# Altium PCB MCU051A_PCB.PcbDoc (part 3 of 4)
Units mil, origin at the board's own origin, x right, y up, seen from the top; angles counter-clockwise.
Board outline 4000 x 6000 mil, 6 copper layers (Top Layer, Signal Layer 1, Signal Layer 2, Signal Layer 3, Signal Layer 4, Bottom Layer), stack 60.4 mil thick; 193 components, 239 nets, 864 pads, 621 vias.
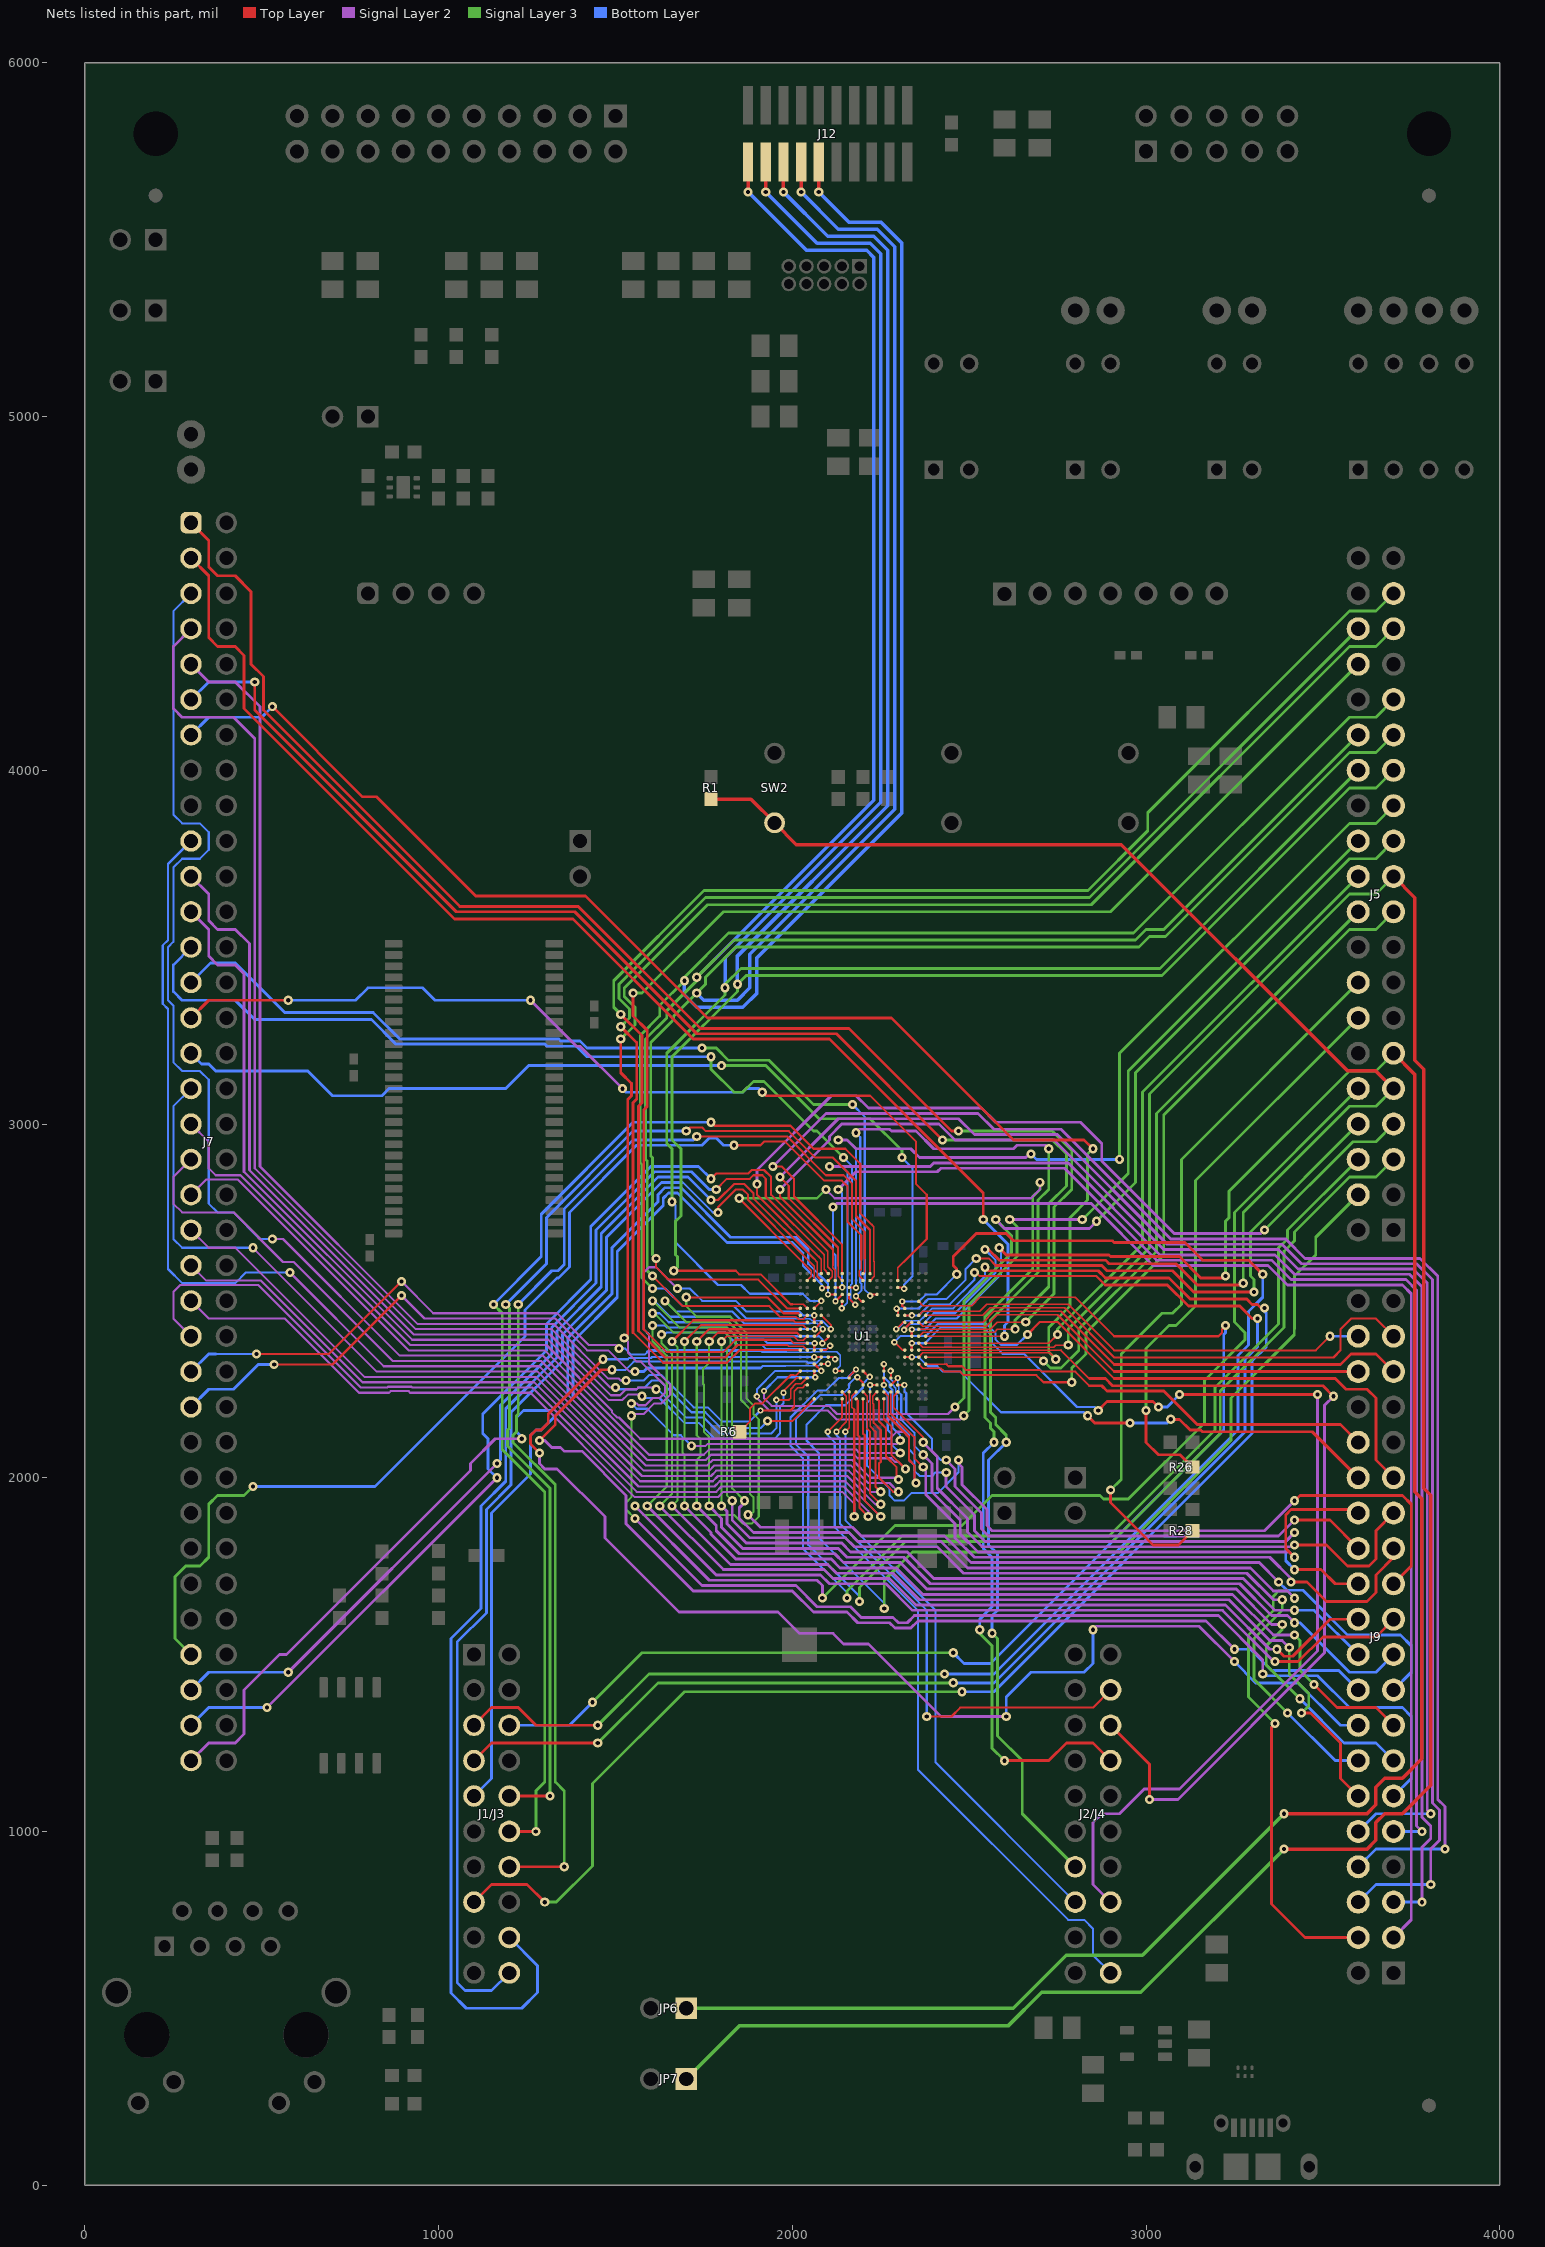
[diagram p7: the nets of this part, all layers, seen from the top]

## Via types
v1: diameter 26, hole 12, Top Layer to Bottom Layer, tented both sides, 517 vias
v2: diameter 18, hole 8, Top Layer to Bottom Layer, tented both sides, 94 vias
v3: diameter 26, hole 12, Top Layer to Bottom Layer, 7 vias
v4: diameter 19.68, hole 7.87, Top Layer to Bottom Layer, 2 vias
v5: diameter 18, hole 8, Top Layer to Bottom Layer, 1 vias

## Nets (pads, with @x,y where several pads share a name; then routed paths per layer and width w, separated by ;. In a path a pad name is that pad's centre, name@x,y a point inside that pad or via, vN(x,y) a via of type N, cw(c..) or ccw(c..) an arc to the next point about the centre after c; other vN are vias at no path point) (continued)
PE5: J1/J3.23 U1.B5 | length 3633.6
  Top Layer w4: U1.B5@2357.48,2498.43 2369.17,2486.74 2506.74,2486.74 2530,2510 2800,2510
  Top Layer w6: 2800,2510 2910,2400 3205,2400 3215,2410 3215,2420 v1(3225,2430)
  Signal Layer 3 w8: v1(1435,1365) 1575,1505 v1(2455,1505)
  Bottom Layer w8: J1/J3.23@1200,1300 1370,1300 v1(1435,1365) ; v1(2455,1505) 2485,1475 2560,1475 3220,2135 3220,2405 3225,2410 v1(3225,2430)
PE6: J9.37 U1.A7 | length 1490.9
  Top Layer w4: U1.A7@2377.17,2459.06 2539.06,2459.06 2560,2480 2770,2480
  Top Layer w6: 2770,2480 2910,2340 3530,2340 3550,2360 3550,2420 3580,2450 3650,2450 J9.37@3700,2400
PE7: J9.38 U1.B7 | length 1325.8
  Top Layer w4: U1.B7@2357.48,2459.06 2358.32,2459.06 2369.26,2470 2530,2470 2550,2490 2780,2490
  Top Layer w6: 2780,2490 2910,2360 3480,2360 v1(3520,2400)
  Bottom Layer w8: v1(3520,2400) J9.38@3600,2400
PF0: J5.28 J12.18 U1.U6 | length 6098.7
  Top Layer w4: v2@2082,2498.54 v2(2082,2500)
  Top Layer w6: U1.U6@2062.2,2478.74 v2@2082,2498.54
  Top Layer w10: v1(1925,5635) J12.18@1925,5719.88
  Signal Layer 3 w8: v1(1660,2780) 1660,2930 1645,2945 1645,3200 1810,3365 v1(1810,3385) 1810,3395 1855,3440 3040,3440 J5.28@3600,4000
  Bottom Layer w6: v1(1660,2780) 1670,2770 1670,2665 1790,2545 1855,2545 1880,2520 2030,2520 2050,2500 v2(2082,2500)
  Bottom Layer w10: v1(1810,3385) 1810,3470 2250,3910 2250,5460 2220,5490 2070,5490 v1(1925,5635)
PF1: J5.27 J12.16 U1.V6 | length 6135.8
  Top Layer w4: 2000,2490.43 2030.83,2490.43 U1.V6@2042.52,2478.74
  Top Layer w6: v1(1665,2585) 1840,2585 1850,2575 1910.43,2575 1995,2490.43 2000,2490.43
  Top Layer w10: v1(1975,5635) J12.16@1975,5719.88
  Signal Layer 3 w8: v1(1665,2585) 1675,2595 1675,2625 1670,2630 1670,2725 1685,2740 1685,2930 1660,2955 1660,3190 1845,3375 v1(1845,3395) 1870,3420 3045,3420 3575,3950 3650,3950 J5.27@3700,4000
  Bottom Layer w10: v1(1845,3395) 1845,3475 2270,3900 2270,5470 2230,5510 2100,5510 v1(1975,5635)
PF2: J5.29 J12.14 U1.W6 | length 6426.8
  Top Layer w6: v1(1615,2620) 1615,2595 1650,2560 1903.74,2560 1985,2478.74 U1.W6@2022.83,2478.74
  Top Layer w10: v1(2025,5635) J12.14@2025,5719.88
  Signal Layer 3 w8: v1(1615,2620) 1605,2630 1605,2905 1600,2910 1600,3230 1665,3295 1665,3305 v1(1730,3370) 1755,3395 1755,3415 1840,3500 2980,3500 3010,3530 3055,3530 3575,4050 3650,4050 J5.29@3700,4100
  Bottom Layer w10: v1(1730,3370) 1750,3350 1845,3350 1880,3385 1880,3480 2290,3890 2290,5480 2240,5530 2130,5530 v1(2025,5635)
PF3: J5.31 J12.12 U1.T7 | length 6824.2
  Top Layer w6: U1.T7@2081.89,2459.06 2109,2431.95 v2(2109,2420)
  Top Layer w10: v1(2075,5635) J12.12@2075,5719.88
  Signal Layer 3 w8: v1(1605,2535) 1575,2565 1575,2885 1570,2890 1570,3250 1625,3305 1625,3335 v1(1695,3405) 1695,3415 1820,3540 2965,3540 3575,4150 3650,4150 J5.31@3700,4200
  Bottom Layer w4: 2020,2450 2049.99,2450 2055.99,2444 2085,2444 v2(2109,2420)
  Bottom Layer w6: v1(1605,2535) 1640,2535 1690,2485 1835,2485 1870,2450 2020,2450
  Bottom Layer w10: v1(1695,3405) 1695,3365 1730,3330 1860,3330 1900,3370 1900,3470 2310,3880 2310,5490 2250,5550 2160,5550 v1(2075,5635)
PF4: J5.30 J12.20 U1.V7 | length 6318.9
  Top Layer w4: 1960,2460 1965,2455 2010,2455 2017.63,2447.37 2030.83,2447.37 U1.V7@2042.52,2459.06
  Top Layer w6: v1(1605,2570) 1690,2485 1935,2485 1960,2460
  Top Layer w10: v1(1875,5635) J12.20@1875,5719.88
  Signal Layer 3 w8: v1(1605,2570) 1590,2585 1590,2895 1585,2900 1585,3240 1645,3300 1645,3320 1730,3405 v1(1730,3415) 1835,3520 2970,3520 3000,3550 3050,3550 J5.30@3600,4100
  Bottom Layer w10: v1(1730,3415) 2230,3915 2230,5450 2210,5470 2040,5470 v1(1875,5635)
PF5: J5.10 U1.W7 | length 4585
  Top Layer w6: v1(1700,2510) 1930,2510 1975,2465 2016.89,2465 U1.W7@2022.83,2459.06
  Signal Layer 2 w8: v1(1555,1920) 1765,1710 2070,1710 2085,1695 v1(2085,1660)
  Signal Layer 3 w6: v1(1555,1920) 1580,1895 1835,1895 1860,1870 1885,1870 1905,1890 1905,2165 1890,2180 1890,2205 1870,2225 1870,2410 1825,2455 1730,2455 1700,2485 v1(1700,2510)
  Signal Layer 3 w8: v1(2085,1660) 2290,1865 2480,1865 2565,1950 2870,1950 2880,1940 2950,1940 3165,2155 3165,2275 3280,2390 3280,2410 3250,2440 3250,2750 J5.10@3600,3100
PF6: J9.4 U1.T8 | length 4292.7
  Top Layer w6: v2(2063,2420) 2081.89,2438.89 U1.T8@2081.89,2439.37
  Top Layer w8: v1(3365,1305) 3355,1295 3355,795 3450,700 J9.4@3600,700
  Signal Layer 2 w8: v1(1865,1935) 1865,1930 1850,1915 1850,1885 1890,1845 2160,1845 2185,1820 2420,1820 2495,1745 3295,1745 3360,1680 3400,1680 3420,1660 v1(3420,1659)
  Signal Layer 3 w6: v1(1605,2500) 1680,2425 1814.69,2425 1840,2399.69 1840,2370 1830,2360 1830,1970 v1(1865,1935)
  Signal Layer 3 w8: v1(3365,1305) 3290,1380 3290,1555 3360,1625 3360,1665 3375,1680 3400,1680 3420,1660 v1(3420,1659)
  Bottom Layer w6: v1(1605,2500) 1610,2500 1655,2455 1825,2455 1860,2420 v2(2063,2420)
PF7: J9.11 U1.U8 | length 4094.5
  Top Layer w6: U1.U8@2062.2,2439.37 v2(2062.2,2459)
  Signal Layer 2 w6: v1(1545,2175) 1550,2180 1580,2180 1610,2210 1630,2210 1655,2235 1655,2263 1595,2323 1595,2405 1580,2420 1580,2580 1595,2595 1615,2595 v1(1675,2535)
  Signal Layer 2 w8: v1(1555,1885) 1745,1695 2010,1695 2070,1635 2165,1635 2195,1605 2285,1605 2300,1590 2325,1590 2345,1610 3205,1610 3330,1485 v1(3330,1445)
  Signal Layer 3 w6: v1(1545,2175) 1545,1945 1530,1930 1530,1910 v1(1555,1885)
  Bottom Layer w6: v1(1675,2535) 1710,2535 1745,2500 1840,2500 1870,2470 2020,2470 2031,2459 v2(2062.2,2459)
  Bottom Layer w8: v1(3330,1445) 3335,1440 3485,1440 3575,1350 3725,1350 3750,1325 3750,1150 J9.11@3700,1100
PG0: J7.49 U1.N15 | length 2107.3
  Top Layer w6: v1(485,2350) 690,2350 v1(895,2555) ; v2@2122.43,2301.57 U1.N15@2140.94,2301.57
  Signal Layer 2 w6: v1(895,2555) 985,2465 1335,2465 1425,2375 1500,2375 v1(1510,2365)
  Bottom Layer w4: 1983,2355 2054.79,2355 2055.79,2356 2126,2356 2136,2346 2136,2316 v2(2122,2302)
  Bottom Layer w6: 370,2350 v1(485,2350) ; v1(1510,2365) 1528,2365 1545,2348 1583,2348 1590,2355 ; 1910,2360 1915,2355 1983,2355
  Bottom Layer w8: J7.49@300,2300 350,2350 370,2350 ; 1590,2355 1595,2360 1910,2360
PG1: J7.51 U1.T14 | length 2049.1
  Top Layer w6: v1(535,2320) 700,2320 v1(895,2515) ; U1.T14@2081.89,2321.26 2100.26,2321.26 v2(2101,2322)
  Signal Layer 2 w6: v1(895,2515) 960,2450 1330,2450 1420,2360 1480,2360 1540,2300 v1(1555,2300)
  Bottom Layer w4: 1980,2316 2074.79,2316 2080.79,2322 v2(2101,2322)
  Bottom Layer w6: 1910,2310 1916,2316 1980,2316
  Bottom Layer w8: J7.51@300,2200 350,2250 420,2250 490,2320 v1(535,2320) ; v1(1555,2300) 1580,2300 1590,2310 1910,2310
PG2: J5.34 U1.V11 | length 3913.5
  Top Layer w4: 1994.46,2390 2003.15,2381.32 ; 2003.15,2380.32 U1.V11@2042.52,2380.32
  Top Layer w6: 1580,2420 1645,2355 1805,2355 1840,2390 1994.46,2390
  Top Layer w8: v1(1550,3370) 1550,3305 1590,3265 1590,3050 1580,3040 1580,2420
  Signal Layer 3 w8: v1(1550,3370) 1575,3370 1805,3600 2900,3600 J5.34@3600,4300
PG3: J5.6 U1.M16 | length 3031
  Top Layer w6: U1.M16@2160.63,2281.89 2160.63,2286.63 v2(2180,2306)
  Signal Layer 3 w8: v1(2155,1660) 2155,1680 2310,1835 2895,1835 3195,2135 3195,2255 3375,2435 3375,2650 3400,2675 3400,2700 J5.6@3600,2900
  Bottom Layer w6: v1(2155,1660) 2155,1675 2030,1800 2030,2055 1995,2090 1995,2170 2071,2246 2095,2246 2130.89,2281.89 2155.89,2281.89 v2(2180,2306)
PG4: J5.5 U1.K17 | length 3109.6
  Top Layer w6: v2(2184,2284) 2200,2268 U1.K17@2200,2262.2
  Signal Layer 3 w8: v1(2190,1650) 2190,1690 2320,1820 2905,1820 3210,2125 3210,2245 3390,2425 3390,2640 3420,2670 3420,2695 3575,2850 3650,2850 J5.5@3700,2900
  Bottom Layer w6: v2(2184,2284) 2179.37,2284 2160.63,2265.26 2160.63,2254.63 2140,2234 2079,2234 2010,2165 2010,2095 2045,2060 2045,1810 2190,1665 v1(2190,1650)
PG5: J5.4 U1.K15 | length 2946.1
  Top Layer w6: U1.K15@2200,2301.57 2216.57,2285 v2(2219,2285)
  Signal Layer 3 w8: v1(2260,1630) 2260,1710 2340,1790 2925,1790 3240,2105 3240,2225 3419,2404 3419,2419.7 3420,2420.7 3420,2570 3480,2630 3480,2680 J5.4@3600,2800
  Bottom Layer w6: v2(2219,2285) 2200,2266 2200,2255 2150,2205 2095,2205 2040,2150 2040,2105 2075,2070 2075,1830 2260,1645 v1(2260,1630)
PG6: J5.37 U1.V12 | length 4244.7
  Top Layer w4: 1986.63,2375 1989.32,2372.32 2030.83,2372.32 2033.76,2369.39 U1.V12@2042.52,2360.63
  Top Layer w6: 1565,2415 1640,2340 1810,2340 1845,2375 1986.63,2375
  Top Layer w8: v1(1515,3310) 1575,3250 1575,3060 1565,3050 1565,2415
  Signal Layer 3 w8: v1(1515,3310) 1495,3330 1495,3405 1750,3660 2835.97,3660 3005,3829.03 3005,3880 3575,4450 3650,4450 J5.37@3700,4500
PG7: J5.24 U1.U14 | length 3093.8
  Top Layer w6: U1.U14@2062.2,2321.26 2062.74,2321.26 v2(2082,2302)
  Signal Layer 2 w6: v2(1900,2230) 1900,2225 1935,2190 2100,2190 2125,2165 2475,2165 v1(2485,2175)
  Signal Layer 2 w8: v1(2615,2730) v1(2820,2730)
  Signal Layer 3 w8: v1(2485,2175) 2500,2190 2500,2490 2635,2625 2635,2710 v1(2615,2730) ; v1(2820,2730) 2950,2860 2950,3150 J5.24@3600,3800
  Bottom Layer w6: v2(1900,2230) 1900,2250 1952,2302 v2(2082,2302)
PH0: J7.71 U1.P4 | length 2969.8
  Top Layer w4: v2(2101,2518) v2@2101.11,2518.11
  Top Layer w6: v2@2101.11,2518.11 U1.P4@2121.26,2518.11
  Signal Layer 2 w8: J7.71@300,1200 350,1250 425,1250 450,1275 450,1400 550,1500 570,1500 1090,2020 1090,2040 1160,2110 v1(1235,2110)
  Bottom Layer w6: 2045,2645 2045,2605 2101,2549 v2(2101,2518)
  Bottom Layer w8: v1@1230,2120 1220,2130 1220,2170 1240,2190 1320,2190 1365,2235 1365,2395 1490,2520 1490,2650 1620,2780 1620,2800 1640,2820 1685,2820 1825,2680 2010,2680 2045,2645
PH1: J7.69 U1.R2 | length 2989.9
  Top Layer w4: 2100,2640 2100,2596.85 2112.5,2584.35 2112.5,2568.4 U1.R2@2101.57,2557.48
  Top Layer w6: v1(1770,2845) 1785,2860 1875,2860 1885,2870 1920,2870 1940,2850 1940,2800 2100,2640
  Signal Layer 2 w8: v1(515,1350) v1(1165,2000)
  Bottom Layer w8: J7.69@300,1300 350,1350 v1(515,1350) ; v1(1165,2000) 1140,2025 1140,2110 1125,2125 1125,2180 1305,2360 1305,2435 1430,2560 1430,2710 1600,2880 1735,2880 v1(1770,2845)
PH2: J7.67 U1.R1 | length 2836.8
  Top Layer w4: 2090,2630 2090,2588.74 U1.R1@2101.57,2577.17
  Top Layer w6: v1(1785,2815) 1815,2845 1880,2845 1890,2855 1915,2855 1925,2845 1925,2795 2090,2630
  Signal Layer 2 w8: v1(575,1450) v1(1165,2040)
  Bottom Layer w8: J7.67@300,1400 350,1450 v1(575,1450) ; v1(1165,2040) 1175,2050 1175,2205 1320,2350 1320,2425 1445,2550 1445,2700 1610,2865 1715,2865 1765,2815 v1(1785,2815)
PH3: J5.7 U1.T1 | length 2574.4
  Top Layer w4: 2075,2625 2081.89,2618.11 U1.T1@2081.89,2577.17
  Top Layer w6: v1(1900,2830) 1900,2800 2075,2625
  Signal Layer 2 w8: v1(1900,2830) 1900,2870 2110,3080 2180,3080 2215,3045 2535,3045 2575,3005 2815,3005 2875,2945 2875,2895 3080,2690 3325,2690 v1(3335,2700)
  Signal Layer 3 w8: v1(3335,2700) 3585,2950 3650,2950 J5.7@3700,3000
PH4: J1/J3.5 U1.R3 | length 2531.7
  Top Layer w6: v2(2084,2536) 2085.8,2537.8 U1.R3@2101.57,2537.8
  Bottom Layer w6: 2030,2635 2030,2600 2084,2546 v2(2084,2536)
  Bottom Layer w8: J1/J3.5@1100,1100 1150,1150 1150,1900 1260,2010 1260,2120 1275,2135 1290,2135 1380,2225 1380,2385 1505,2510 1505,2640 1635,2770 1635,2790 1650,2805 1675,2805 1815,2665 2000,2665 2030,2635
PH5: J1/J3.29 U1.T2 | length 3671.8
  Top Layer w4: 2060,2620 2070.2,2609.8 2070.2,2570 2081.89,2558.32 U1.T2@2081.89,2557.48
  Top Layer w6: v1(1770,2785) 1790,2785 1835,2830 1865,2830 1890,2805 1890,2790 2060,2620
  Bottom Layer w8: J1/J3.29@1200,700 1280,620 1280,545 1235,500 1078,500 1035,543 1035,1545 1120,1630 1120,1920 1190,1990 1190,2195 1335,2340 1335,2415 1460,2540 1460,2690 1620,2850 1705,2850 v1(1770,2785)
PH6: J1/J3.30 U1.U2 | length 3321.4
  Top Layer w4: 2030,2630 2062.2,2597.8 U1.U2@2062.2,2557.48
  Top Layer w6: v1(1790,2750) 1790,2765 1840,2815 1860,2815 1875,2800 1875,2785 2030,2630
  Bottom Layer w6: 1690,2835 1775,2750 v1(1790,2750)
  Bottom Layer w8: J1/J3.30@1200,600 1150,550 1075,550 1052.5,572.5 1052.5,1535 1135,1617.5 1135,1910 1205,1980 1205,2185 1350,2330 1350,2405 1475,2530 1475,2680 1630,2835 1690,2835
PH7: J2/J4.17 U1.V2 | length 3340.3
  Top Layer w4: 2030,2609.2 2054.2,2585 2054.2,2570 2042.52,2558.31 U1.V2@2042.52,2557.48
  Top Layer w6: v1(1850,2790) 1850,2789.2 2030,2609.2
  Top Layer w8: v1(2600,1200) 2725,1200 2775,1250 2850,1250 J2/J4.17@2900,1200
  Signal Layer 2 w6: v1(2095,2815) 2120,2790 2675,2790 2700,2815 v1(2700,2835)
  Signal Layer 3 w6: v1(1850,2790) 2070,2790 v1(2095,2815)
  Signal Layer 3 w8: v1(2530,1570) 2530,1560 2565,1525 2565,1235 v1(2600,1200) ; v1(2570,2100) 2570,2130 2560,2140 2560,2155 2545,2170 2545,2455 2680,2590 2680,2795 2700,2815 v1(2700,2835)
  Bottom Layer w8: v1(2530,1570) 2530,1600 2565,1635 2565,1775 2540,1800 2540,2070 v1(2570,2100)
PJ0: J5.9 R1.1 SW2.2 U1.C8 | length 4247
  Top Layer w6: v2@2316,2419.63 2335.74,2439.37 U1.C8@2337.8,2439.37
  Top Layer w8: v1(2545,2645) 2555,2645 2585,2615 2885,2615 2895,2605 3085,2605 3145,2545 3270,2545 v1(3275,2550)
  Top Layer w10: R1.1@1770,3918.51 1883.07,3918.51 SW2.2@1950,3851.58 2011.58,3790 2930,3790 3570,3150 3650,3150 J5.9@3700,3100
  Signal Layer 3 w8: v1(3275,2550) 3275,2750 3575,3050 3650,3050 J5.9@3700,3100
  Bottom Layer w6: v2(2316,2418) 2316,2419.63 2331.37,2435 2370,2435 2400,2465 2460,2465 2575,2580 2575,2615 v1(2545,2645)
PJ1: J5.8 U1.E7 | length 1746.7
  Top Layer w6: U1.E7@2298.43,2459.06 v2@2298.43,2474.57 ; v1(2520,2620) 2555,2620 2575,2600
  Top Layer w8: 2575,2600 2875,2600 2890,2585 3075,2585 3135,2525 v1(3305,2525)
  Signal Layer 3 w8: v1(3305,2525) 3305,2560 3295,2570 3295,2695 J5.8@3600,3000
  Bottom Layer w6: v2(2295,2478) 2356.74,2478 2383.74,2505 2435,2505 2490,2560 2490,2590 v1(2520,2620)
PJ2: J9.23 U1.H17 | length 2352.3
  Top Layer w6: v2(2220,2262) 2220.2,2262.2 U1.H17@2239.37,2262.2
  Top Layer w8: v1(3420,1935) 3435,1950 3725,1950 3750,1925 3750,1750 J9.23@3700,1700
  Signal Layer 2 w8: v1(2470,2050) 2470,2040 2480,2030 2480,1980 2550,1910 2550,1865 2565,1850 3335,1850 v1(3420,1935)
  Bottom Layer w6: v2(2220,2262) 2220,2220 2211.69,2211.69 2211.69,2033.31 2275,1970 2275,1950 2290,1935 2315,1935 2336.5,1956.5 2411.5,1956.5 2470,2015 v1(2470,2050)
PJ3: J9.24 U1.F16 | length 1878.7
  Top Layer w6: v2(2278,2302) 2278.74,2301.26 U1.F16@2278.74,2281.89
  Top Layer w8: v1(3420,1740) 3495,1740 3535,1700 J9.24@3600,1700
  Signal Layer 2 w8: v1(2435,2015) 2435,1975 2515,1895 2515,1850 2545,1820 3395,1820 v1(3420,1845)
  Bottom Layer w4: v2(2278,2302) 2278,2278.36 2284,2272.36 2284,2262.2 2293,2253.2 2293,2235 2296,2232
  Bottom Layer w6: 2296,2232 2296,2154 2330,2120 2330,2080 2345,2065 2345,2020 2360,2005 2395,2005 2405,2015 v1(2435,2015)
  Bottom Layer w8: v1(3420,1740) 3395,1765 3395,1820 v1(3420,1845)
PJ4: J9.25 U1.F18 | length 1914.1
  Top Layer w4: U1.F18@2278.74,2242.52 2278.74,2181.26 2345,2115
  Top Layer w6: 2345,2115 2345,2055 v1(2370,2030)
  Top Layer w8: v1(3410,1705) 3455,1705 3510,1650 3625,1650 3650,1675 3650,1725 3700,1775 J9.25@3700,1800
  Signal Layer 2 w8: v1(2370,2030) 2377.5,2022.5 2377.5,1952.5 2460,1870 2460,1830 2515,1775 3350,1775 3410,1715 v1(3410,1705)
PJ5: J9.26 U1.E17 | length 1649.8
  Top Layer w6: U1.E17@2298.43,2262.2 2316.8,2262.2 v2(2317,2262)
  Top Layer w8: v1(3420,1880) 3520,1880 J9.26@3600,1800
  Signal Layer 2 w8: v1(2435,2050) 2460,2025 2460,1975 2535,1900 2535,1855 2555,1835 3375,1835 v1(3420,1880)
  Bottom Layer w6: v2(2317,2262) 2317,2243.63 2322,2238.63 2322,2183 2395,2110 2395,2075 2420,2050 v1(2435,2050)
PJ6: J9.8 U1.N1 | length 4425.3
  Top Layer w6: v1(1945,2880) 1970,2880 2005,2845 2005,2795 2140.94,2659.06 U1.N1@2140.94,2577.17
  Signal Layer 2 w8: v1(1945,2880) 2095,3030 2525,3030 2570,2985 2760,2985 3070,2675 3395,2675 3450,2620 3775,2620 3825,2570 3825,1090 3845,1070 v1(3845,950)
  Bottom Layer w8: J9.8@3600,900 3650,950 v1(3845,950)
PJ7: J2/J4.34 U1.K5 | length 3333.1
  Top Layer w6: v2(2180,2513) 2194.57,2498.43 U1.K5@2200,2498.43
  Signal Layer 2 w8: v1(2180,2975) 2190,2985 2275,2985 2280,2980 2350,2980 2400,2930 2625,2930 2635,2940 2715,2940 v1(2725,2930)
  Signal Layer 3 w8: v1(2565,1560) 2580,1545 2580,1270 2650,1200 2650,1050 J2/J4.34@2800,900 ; v1(2605,2100) 2605,2120 2575,2150 2575,2170 2560,2185 2560,2445 2695,2580 2695,2785 2725,2815 v1(2725,2930)
  Bottom Layer w6: v2(2180,2513) 2180,2514.37 2196,2530.37 2196,2547.63 2192,2551.63 2192,2963 v1(2180,2975)
  Bottom Layer w8: v1(2565,1560) 2565,1610 2580,1625 2580,1785 2555,1810 2555,2050 v1(2605,2100)
PK0: J1/J3.25 U1.J1 | length 3175.6
  Top Layer w6: v1(1700,2980) 1710,2990 1745,2990 1755,2980 1990,2980 2065,2905 2115,2905 2180,2840 2180,2740 2219.69,2700.31 U1.J1@2219.69,2577.17
  Top Layer w8: J1/J3.25@1200,1100 v1(1315,1100)
  Signal Layer 3 w8: v1(1190,2490) 1200,2480 1200,2140 1195,2135 1195,2090 1315,1970 v1(1315,1100)
  Bottom Layer w8: v1(1190,2490) 1305,2605 1305,2735 1550,2980 v1(1700,2980)
PK1: J1/J3.26 U1.J2 | length 3356.2
  Top Layer w4: U1.J2@2219.69,2557.48 2231.37,2569.17 2231.37,2610 2230,2611.37 2230,2710 2225,2715
  Top Layer w6: v1(1770,3005) 1780,2995 1995,2995 2060,2930 2150,2930 2192,2888 2192,2748 2225,2715
  Top Layer w8: J1/J3.26@1200,1000 v1(1275,1000)
  Signal Layer 3 w8: v1(1155,2490) 1180,2465 1180,2080 1300,1960 1300,1140 1275,1115 v1(1275,1000)
  Bottom Layer w8: v1(1155,2490) 1290,2625 1290,2745 1550,3005 v1(1770,3005)
PK2: J1/J3.27 U1.K1 | length 3370.9
  Top Layer w4: U1.K1@2200,2577.17 2205,2582.17 2205,2620
  Top Layer w6: v1(1730,2965) 1985,2965 2095,2855 2145,2855 2169,2831 2169,2731 2205,2695 2205,2620
  Top Layer w8: J1/J3.27@1200,900 v1(1355,900)
  Signal Layer 3 w8: v1(1225,2490) 1225,2180 1220,2175 1220,2130 1210,2120 1210,2100 1330,1980 1330,1140 1355,1115 v1(1355,900)
  Bottom Layer w8: v1(1225,2490) 1320,2585 1338.03,2585 1355,2601.97 1355,2760 1550,2955 1720,2955 v1(1730,2965)
PK3: J7.65 U1.K2 | length 3229.6
  Top Layer w4: 2195,2615 2195,2590 2189.08,2584.08 2189.08,2570.92 2200,2560 U1.K2@2200,2557.48
  Top Layer w6: v1(1835,2940) 1910,2940 1920,2950 1980,2950 2090,2840 2140,2840 2156,2824 2156,2724 2195,2685 2195,2615
  Signal Layer 3 w8: J7.65@300,1500 255,1545 255,1720 285,1750 325,1750 350,1775 350,1925 375,1950 450,1950 v1(475,1975)
  Bottom Layer w8: v1(475,1975) 820,1975 1244.01,2399.01 1244.01,2474.01 1335,2565 1339.01,2565 1370,2595.99 1370,2750 1560,2940 1745,2940 1765,2960 1785,2960 1805,2940 v1(1835,2940)
PK4: J7.7 U1.U19 | length 3667.6
  Top Layer w6: v1(1930,2160) 1999.37,2160 U1.U19@2062.2,2222.83
  Signal Layer 2 w6: 480,2875 935,2420 1320,2420 1485,2255 v1(1500,2255)
  Signal Layer 2 w8: J7.7@300,4400 250,4350 250,4175 275,4150 420,4150 480,4090 480,2875
  Bottom Layer w6: v1(1500,2255) 1505,2250 1560,2250 1565,2255 1582.5,2255 1602.5,2275 1625,2275 1715,2185 1753.79,2185 1798.79,2140 1910,2140 v1(1930,2160)
PK5: J7.9 U1.V17 | length 3472.8
  Top Layer w4: 2005,2200 2005,2245 2015,2255 2030,2255 2037.2,2262.2 U1.V17@2042.52,2262.2
  Top Layer w6: v2(1910,2190) 1995,2190 2005,2200
  Signal Layer 2 w6: 495,2880 940,2435 1325,2435 1480,2280 1510,2280 1515,2275 v1(1530,2275)
  Signal Layer 2 w8: J7.9@300,4300 350,4250 425,4250 495,4180 495,2880
  Bottom Layer w6: v1(1530,2275) 1580,2275 1595,2290 1630,2290 1721.21,2198.79 1761.21,2198.79 1801.46,2158.54 1878.54,2158.54 v2(1910,2190)
PK6: J7.21 U1.V16 | length 2958.5
  Top Layer w4: 1990,2220 1995,2225 1995,2250 2010,2265 2025.63,2265 U1.V16@2042.52,2281.89
  Top Layer w6: v2(1955,2220) 1990,2220
  Signal Layer 2 w6: 465,2870 930,2405 1315,2405 1487,2233 1513,2233 1530,2250 1560,2250 1565,2255 1610,2255 v1(1615,2250)
  Signal Layer 2 w8: J7.21@300,3700 350,3650 350,3575 375,3550 425,3550 465,3510 465,2870
  Bottom Layer w6: v1(1615,2250) 1620,2250 1700.18,2169.82 1750.18,2169.82 1795,2125 1940,2125 1955,2140 v2(1955,2220)
PK7: J7.23 U1.W16 | length 2847.8
  Top Layer w4: v2(1975,2240) 1975,2245 2011.89,2281.89 U1.W16@2022.83,2281.89
  Signal Layer 2 w6: 450,2865 925,2390 1310,2390 1480,2220 1520,2220 1535,2235 1570,2235 v1(1575,2230)
  Signal Layer 2 w8: J7.23@300,3600 350,3550 350,3475 375,3450 425,3450 450,3425 450,2865
  Bottom Layer w6: v1@1585.36,2225.36 1624.64,2225.36 1695,2155 1735.36,2155 1780.36,2110 1950,2110 1965,2125 1965,2200 1975,2210 v2(1975,2240)
PL0: J7.39 U1.G16 | length 2586.4
  Top Layer w6: v2(2259,2262) 2259.06,2262.06 U1.G16@2259.06,2281.89
  Signal Layer 2 w6: J7.39@300,2800 343,2843 432,2843 915,2360 1300,2360 1595,2065 1750,2065 1765,2080 2180,2080 2190,2070 v1(2305,2070)
  Bottom Layer w6: v2(2259,2262) 2259,2251 2270,2240 2270,2135 2280,2125 2280,2095 v1(2305,2070)
PL1: J7.37 U1.H19 | length 2784.2
  Top Layer w6: U1.H19@2239.37,2222.83 2245,2217.2 2245,2160 2265,2140 2265,2060 2295,2030 2295,2000 v1(2300,1995)
  Signal Layer 2 w6: J7.37@300,2900 250,2850 250,2775 275,2750 420,2750 560,2610 590,2610 870,2330 1290,2330 1585,2035 1760,2035 1775,2050 2170,2050 2220,2000 2295,2000 v1(2300,1995)
PL2: J7.35 U1.G18 | length 2893.5
  Top Layer w4: U1.G18@2259.06,2242.52 2270.74,2230.83 2270.74,2174.26
  Top Layer w6: 2270.74,2174.26 2330,2115 2330,2050 2345,2035 2345,1990 v1(2350,1985)
  Signal Layer 2 w6: J7.35@300,3000 350,2950 350,2875 370,2855 440,2855 920,2375 1305,2375 1490,2190 1490,2185 1505,2170 1510,2170 1570,2110 2275,2110 2295,2130 2315,2130 2330,2115 2330,2050 2345,2035 2345,1990 v1(2350,1985)
PL3: J7.33 U1.J18 | length 3049.4
  Top Layer w4: U1.J18@2219.69,2242.52 2219.69,2145.31 2235,2130
  Top Layer w6: 2235,2130 2235,1975 v1(2250,1960)
  Signal Layer 2 w6: v1(475,2650) 825,2300 1280,2300 1575,2005 1770,2005 1785,2020 2160,2020 2220,1960 v1(2250,1960)
  Bottom Layer w6: J7.33@300,3100 250,3050 250,2675 275,2650 v1(475,2650)
PL4: J7.19 U1.H18 | length 3942.8
  Top Layer w4: 2230,2208.15 2227.69,2210.46 2227.69,2230.83 U1.H18@2239.37,2242.52
  Top Layer w6: 2230,2208.15 2230,2155 2250,2135 2250,2045 2245,2040 2245,2000 2285,1960 v1(2300,1960)
  Signal Layer 2 w6: v1(580,2580) 845,2315 1285,2315 1580,2020 1765,2020 1780,2035 2165,2035 2215,1985 2275,1985 v1(2300,1960)
  Bottom Layer w6: J7.19@300,3800 235,3735 235,3520 220,3505 220,3340 235,3325 235,2590 275,2550 425,2550 455,2580 v1(580,2580)
PL5: J7.5 U1.G19 | length 4486.4
  Top Layer w4: 2259.06,2165.94 U1.G19@2259.06,2222.83
  Top Layer w6: 2259.06,2165.94 2280,2145 2280,2065 v1(2320,2025)
  Signal Layer 2 w6: v1(530,2675) 560,2675 890,2345 1295,2345 1590,2050 1755,2050 1770,2065 2175,2065 2185,2055 2280,2055 2290,2045 2300,2045 v1(2320,2025)
  Bottom Layer w6: J7.5@300,4500 250,4450 250,3875 275,3850 325,3850 350,3825 350,3775 325,3750 275,3750 250,3725 250,3515 235,3500 235,3350 250,3335 250,3175 275,3150 325,3150 350,3125 350,2775 375,2750 420,2750 495,2675 v1(530,2675)
PL6_EXT: J5.16 R28.1 | length 2075.3
  Top Layer w8: v1(2900,1965) 2900,1930 3020,1810 3091.5,1810 R28.1@3131.5,1850
  Signal Layer 3 w8: v1(2900,1965) 2930,1995 2930,2350 3045,2465 3075,2465 3100,2490 3100,2900 J5.16@3600,3400
PL7_EXT: J5.14 R26.1 | length 1620.7
  Top Layer w8: v1(3000,2190) 3000,2100 3035,2065 3096.5,2065 R26.1@3131.5,2030
  Signal Layer 3 w8: v1(3000,2190) 3000,2365 3065,2430 3085,2430 3140,2485 3140,2840 J5.14@3600,3300
PM0: J7.41 U1.K18 | length 2621.7
  Top Layer w4: U1.K18@2200,2242.52 2211.69,2230.83 2211.69,2138.31
  Top Layer w6: 2211.69,2138.31 2220,2130 2220,1955 v1(2250,1925)
  Signal Layer 2 w6: J7.41@300,2700 350,2650 425,2650 790,2285 1275,2285 1570,1990 1775,1990 1790,2005 2155,2005 2235,1925 v1(2250,1925)
PM1: J7.43 U1.K19 | length 2610.1
  Top Layer w6: U1.K19@2200,2222.83 2200,2125 2205,2120 2205,1935 v1(2250,1890)
  Signal Layer 2 w6: J7.43@300,2600 343,2557 498,2557 785,2270 1270,2270 1565,1975 1780,1975 1795,1990 2150,1990 v1(2250,1890)
PM2: J7.45 U1.L18 | length 2525.3
  Top Layer w4: 2175,2193.31 2168.63,2199.68 2168.63,2230.83 U1.L18@2180.32,2242.52
  Top Layer w6: v1(2175,1890) 2175,2193.31
  Signal Layer 2 w6: J7.45@300,2500 350,2450 565,2450 775,2240 860,2240 865,2245 915,2245 920,2240 1260,2240 1555,1945 1790,1945 1805,1960 2141.02,1960 2175,1926.02 v1(2175,1890)
PM3: J7.47 U1.L19 | length 2760.4
  Top Layer w6: U1.L19@2180.32,2222.83 2185,2218.15 2185,2120 2190,2115 2190,1915 v1(2215,1890)
  Signal Layer 2 w6: J7.47@300,2400 250,2450 250,2525 270,2545 490,2545 780,2255 855,2255 857,2257 923,2257 925,2255 1265,2255 1560,1960 1785,1960 1800,1975 2145,1975 2215,1905 v1(2215,1890)
PM4: J2/J4.33 U1.M18 | length 1706.2
  Top Layer w4: v2(2150,2130) 2160.63,2140.63 U1.M18@2160.63,2242.52
  Bottom Layer w6: 2150,2120 2150,1880 2405,1625 2405,1195 J2/J4.33@2800,800
PM5: J5.35 U1.G15 | length 5026.7
  Top Layer w6: v1(1525,2395) 1535,2405 ; U1.G15@2259.06,2301.57 v2@2259.06,2320.94
  Top Layer w8: v1(1515,3240) 1515,3145 1545,3115 1545,3080 1535,3070 1535,2405
  Signal Layer 2 w6: v1(1525,2395) 1535,2385 1535,2353 1560,2328 1572,2328 1640,2260 1640,2240 1625.36,2225.36 1605.36,2225.36 1585,2205 1565,2205 1560,2210 v1(1545,2210) ; v1(1715,2090) 1755,2090 1760,2095 2295,2095 v1(2305,2105)
  Signal Layer 3 w8: v1(1515,3240) 1555,3280 1555,3330 1525,3360 1525,3385 1760,3620 2845,3620 3575,4350 3650,4350 J5.35@3700,4400
  Bottom Layer w6: v1(1545,2210) 1560,2195 1590,2195 1665,2120 1685,2120 v1(1715,2090) ; v2(2259,2321) 2259,2284.63 2275,2268.63 2275,2257 2283,2249 2283,2142 2305,2120 v1(2305,2105)
PM6: J2/J4.11 U1.N19 | length 1987.5
  Top Layer w6: v2(2100,2130) 2140.94,2170.94 U1.N19@2140.94,2222.83
  Bottom Layer w6: 2100,2120 2120,2100 2120,1860 2355,1625 2355,1175 2780,750 2825,750 2850,725 2850,650 J2/J4.11@2900,600
PM7: J2/J4.19 U1.N18 | length 1580.5
  Top Layer w4: v2(2125,2130) 2152.63,2157.63 2152.63,2230.83 U1.N18@2140.94,2242.52
  Top Layer w6: v1(2380,1325) 2450,1325 2475,1350 2850,1350 J2/J4.19@2900,1400
  Bottom Layer w6: 2125,2120 2135,2110 2135,1870 2380,1625 v1(2380,1325)
PN0: J5.11 JP6.1 U1.C10 | length 6389.9
  Top Layer w6: U1.C10@2337.8,2400 v2@2337.8,2418.8
  Top Layer w8: v1(2585,2650) 2605,2630 2895,2630 2900,2625 3095,2625 3155,2565 3220,2565 v1(3225,2570)
  Top Layer w10: v1(3390,1050) 3625,1050 3650,1075 3650,1125 3675,1150 3725,1150 3780,1205 3780,1940 3760,1960 3760,3140 J5.11@3700,3200
  Signal Layer 3 w8: v1(3225,2570) 3225,2725 3235,2735 3235,2810 3575,3150 3650,3150 J5.11@3700,3200
  Signal Layer 3 w10: JP6.1@1700,500 2625,500 2775,650 2990,650 v1(3390,1050)
  Bottom Layer w6: v2(2338,2419) 2375,2419 2406,2450 2465,2450 2590,2575 2590,2645 v1(2585,2650)
PN1: J5.21 JP7.1 U1.B11 | length 7271.6
  Top Layer w4: U1.B11@2357.48,2380.32 2369.17,2368.63 2738.63,2368.63 2745,2375 v1(2780,2375)
  Top Layer w10: v1(3390,950) 3625,950 3650,975 3650,1025 3675,1050 3725,1050 3805,1130 3805,1950 3785,1970 3785,3155 3760,3180 3760,3640 J5.21@3700,3700
  Signal Layer 3 w8: v1(2780,2375) 2780,2420 3010,2650 3010,3085 3575,3650 3650,3650 J5.21@3700,3700
  Signal Layer 3 w10: JP7.1@1700,300 1850,450 2610,450 2705,545 2985,545 v1(3390,950)
PN2: J5.22 U1.A11 | length 2030.1
  Top Layer w4: U1.A11@2377.17,2380.32 2725.32,2380.32
  Top Layer w6: 2725.32,2380.32 v1(2750,2405)
  Signal Layer 3 w8: v1(2750,2405) 2750,2420 2990,2660 2990,3090 J5.22@3600,3700
PN3: J7.11 U1.B10 | length 3931.4
  Top Layer w4: U1.B10@2357.48,2400 2358.31,2400 2370,2411.69 2571.69,2411.69 2580,2420 v1(2630,2420)
  Top Layer w8: v1(480,4250) 480,4170 1050,3600 1385,3600 1730,3255 2125,3255 v1(2425,2955)
  Signal Layer 3 w8: v1(2425,2955) 2735,2955 2775,2915 2775,2825 2725,2775 2725,2540 2630,2445 v1(2630,2420)
  Bottom Layer w8: J7.11@300,4200 350,4250 v1(480,4250)
PN4: J7.3 U1.A10 | length 3834.9
  Top Layer w4: U1.A10@2377.17,2400 v1(2600,2400)
  Top Layer w8: J7.3@300,4600 350,4550 350,4375 375,4350 425,4350 450,4325 450,4175 1045,3580 1380,3580 1720,3240 2105,3240 2540,2805 v1(2540,2730)
  Bottom Layer w8: v1(2540,2730) 2610,2660 2610,2440 2600,2430 v1(2600,2400)
PN5: J7.1 U1.B9 | length 4294.7
  Top Layer w4: U1.B9@2357.48,2419.69 2559.69,2419.69 2580,2440 v1(2660,2440)
  Top Layer w8: J7.1@300,4700 350,4650 350,4575 375,4550 425,4550 470,4505 470,4300 505,4265 505,4170 1060,3615 1395,3615 1740,3270 2160,3270 2450,2980 v1(2470,2980)
  Signal Layer 3 w8: v1(2470,2980) 2735,2980 2790,2925 2790,2815 2740,2765 2740,2520 v1(2660,2440)
PN6: J9.22 U1.T12 | length 3241.9
  Top Layer w6: U1.T12@2081.89,2360.63 2094.63,2360.63 v2(2107,2373)
  Top Layer w8: v1(3370,1515) 3390,1495 3415,1495 3520,1600 J9.22@3600,1600
  Signal Layer 2 w8: v1(1625,1920) 1805,1740 2090,1740 2115,1715 2275,1715 2350,1640 3225,1640 3350,1515 v1(3370,1515)
  Signal Layer 3 w6: v1(1625,1920) 1660,1955 1660,2350 1630,2380 v1(1630,2405)
  Bottom Layer w4: 1915,2375 1925,2365 2099,2365 v2(2107,2373)
  Bottom Layer w6: v1(1630,2405) 1635,2400 1645,2410 1810,2410 1845,2375 1915,2375
PN7: J9.21 U1.U12 | length 3389.7
  Top Layer w6: U1.U12@2062.2,2360.63 2062.2,2379.2 v2(2063,2380)
  Top Layer w8: v1(3365,1480) 3430,1480 3500,1550 3650,1550 J9.21@3700,1600
  Signal Layer 2 w8: v1(1590,1920) 1785,1725 2080,1725 2105,1700 2265,1700 2340,1625 3216,1625 3361,1480 v1(3365,1480)
  Signal Layer 3 w6: v1(1590,1920) 1645,1975 1645,2345 1605,2385 v1(1605,2430)
  Bottom Layer w6: v1(1605,2430) 1640,2430 1645,2425 1814.69,2425 1849.69,2390 1920,2390 1930,2380 v2(2063,2380)
PP0: J1/J3.3 U1.D6 | length 4228.1
  Top Layer w6: v2(2311,2498) 2311,2485.85 U1.D6@2318.11,2478.74
  Top Layer w8: J1/J3.3@1100,1300 1150,1350 1225,1350 1275,1300 v1(1450,1300) ; v1(2465,2575) 2465,2590 2455,2600 2455,2625 2520,2690 2605,2690 2625,2670 2905,2670 2910,2665 3110,2665 3160,2615 3290,2615 v1(3330,2575)
  Signal Layer 3 w8: v1(1450,1300) 1595,1445 v1(2430,1445)
  Bottom Layer w6: v2(2311,2498) 2358,2498 2377.64,2517.64 2407.64,2517.64 v1(2465,2575)
  Bottom Layer w8: v1(2430,1445) 2570,1445 3260,2135 3260,2345 3290,2375 3290,2470 3330,2510 v1(3330,2575)
PP1: J1/J3.4 U1.D7 | length 4012.3
  Top Layer w6: U1.D7@2318.11,2459.06 2337.94,2459.06 v2(2338,2459) ; v1(2515,2580) 2520,2580 2530,2570 2860,2570 2885,2545
  Top Layer w8: J1/J3.4@1100,1200 1150,1250 v1(1450,1250) ; 2885,2545 3060,2545 3120,2485 3265,2485 3300,2450 v1(3315,2450)
  Signal Layer 3 w8: v1(1450,1250) 1620,1420 v1(2455,1420)
  Bottom Layer w6: v2(2338,2459) 2358.26,2459 2389.26,2490 2445,2490 2515,2560 v1(2515,2580)
  Bottom Layer w8: v1(2455,1420) 2570,1420 3280,2130 3280,2335 3315,2370 v1(3315,2450)
PP2: J7.13 U1.B13 | length 4155.6
  Top Layer w4: U1.B13@2357.48,2340.94 2369.17,2352.63 2727.37,2352.63 v1(2745,2335)
  Top Layer w8: v1(530,4180) 785,3925 825,3925 1105,3645 1415,3645 1760,3300 2280,3300 2625,2955 2825,2955 v1(2850,2930)
  Signal Layer 3 w8: v1(2745,2335) 2725,2355 2725,2425 2785,2485 2785,2735 2835,2785 2835,2915 v1(2850,2930)
  Bottom Layer w8: J7.13@300,4100 350,4150 500,4150 v1(530,4180)
PP3: J2/J4.13 U1.C12 | length 3131.3
  Top Layer w6: U1.C12@2337.8,2360.63 v2@2337.8,2379.8
  Top Layer w8: v1(2865,2190) 2890,2215 3020,2215 v1(3035,2200) ; v1(3095,2235) v1(3485,2235)
  Signal Layer 2 w8: J2/J4.13@2900,800 2850,850 2850,1025 2875,1050 2925,1050 2995,1120 3095,1120 3485,1510 v1(3485,2235)
  Bottom Layer w6: v2(2338,2380) 2375,2380 2420,2425 2539.69,2425 2565,2399.69 2565,2380 2595,2350 2655,2350 2805,2200 2855,2200 v1(2865,2190)
  Bottom Layer w8: v1(3035,2200) 3060,2200 v1(3095,2235)
PP4: J1/J3.8 U1.D8 | length 4508.8
  Top Layer w6: v2(2294,2420) 2313.37,2439.37 U1.D8@2318.11,2439.37
  Top Layer w8: J1/J3.8@1100,800 1150,850 1250,850 v1(1300,800) ; v1(2545,2595) 2555,2585 2865,2585 2885,2565 3065,2565 3125,2505 3285,2505 3300,2490 3315,2490 3325,2480 v1(3335,2480)
  Signal Layer 3 w8: v1(1300,800) 1332.63,800 1435,902.37 1435,1135 1695,1395 v1(2480,1395)
  Bottom Layer w4: v2(2294,2420) 2296.79,2420 2320.79,2444 2361,2444 2368,2451
  Bottom Layer w6: 2368,2451 2395.74,2478.74 2455,2478.74 2545,2568.74 v1(2545,2595)
  Bottom Layer w8: v1(2480,1395) 2570,1395 3300,2125 3300,2330 3340,2370 3340,2465 3335,2470 v1(3335,2480)
PP5: J2/J4.18 U1.B12 | length 2884.4
  Top Layer w4: U1.B12@2357.48,2360.63 2759.37,2360.63
  Top Layer w6: 2759.37,2360.63 2840,2280
  Top Layer w8: 2840,2280 2885,2280 2905,2260 3500,2260 v1(3530,2230) ; J2/J4.18@2900,1300 3010,1190 v1(3010,1090)
  Signal Layer 2 w8: v1(3010,1090) 3090,1090 3505,1505 3505,2205 v1(3530,2230)
PP6: J9.36 U1.B8 | length 1327
  Top Layer w4: U1.B8@2357.48,2439.37 2369.17,2427.69 2547.69,2427.69 2580,2460 2750,2460
  Top Layer w6: 2750,2460 2910,2300
  Top Layer w8: 2910,2300 J9.36@3600,2300
PP7: J9.35 U1.A8 | length 1430.8
  Top Layer w4: U1.A8@2377.17,2439.37 2539.37,2439.37 2570,2470 2760,2470
  Top Layer w6: 2760,2470 2910,2320
  Top Layer w8: 2910,2320 3550,2320 3580,2350 3650,2350 J9.35@3700,2300
PQ0: J7.31 U1.E3 | length 2626.8
  Top Layer w6: U1.E3@2298.43,2537.8 2312.2,2537.8 v2(2316,2534)
  Signal Layer 3 w8: v1(1800,3165) 1925,3165 2075,3015 2220,3015 2310,2925 v1@2310,2910
  Bottom Layer w6: v1@2310,2910 v1(2310,2905) 2340,2875 2340,2570 2316,2546 v2(2316,2534)
  Bottom Layer w8: J7.31@300,3200 330,3170 350,3170 370,3150 630,3150 700,3080 840,3080 860,3100 1190,3100 1255,3165 v1(1800,3165)
PQ1: J7.29 U1.E2 | length 2712.4
  Top Layer w4: U1.E2@2298.43,2557.48 2298.43,2593.43 2315,2610
  Top Layer w6: v1(1915,3090) 1925,3080 2220,3080 2350,2950 2350,2830 2380,2800 2380,2675 2315,2610
  Top Layer w8: J7.29@300,3300 350,3350 v1(575,3350)
  Signal Layer 2 w8: v1(1260,3350) 1390,3220 1400,3220 v1(1520,3100)
  Bottom Layer w8: v1(575,3350) 765,3350 800,3385 955,3385 990,3350 v1(1260,3350) ; v1(1520,3100) 1530,3090 1860,3090 1870,3100 1905,3100 v1(1915,3090)
PQ2: J7.27 U1.H4 | length 2641.3
  Top Layer w6: v2(2220,2514) 2224.11,2518.11 U1.H4@2239.37,2518.11
  Signal Layer 3 w8: v1(1745,3215) 1785,3215 1820,3180 1935,3180 2060,3055 v1(2170,3055)
  Bottom Layer w4: 2205,2556 2205,2531.79 2220,2516.79 v2(2220,2514)
  Bottom Layer w6: v1(2170,3055) 2205,3020 2205,2556
  Bottom Layer w8: J7.27@300,3400 355,3455 425,3455 565,3315 815,3315 890,3240 1340,3240 1345,3235 1400,3235 1420,3215 v1(1745,3215)
PQ3: J7.25 U1.M4 | length 2750
  Top Layer w6: U1.M4@2160.63,2518.11 2160.63,2506.37 v2(2178,2489)
  Signal Layer 3 w8: v1(1770,3190) 1770,3155 1835,3090 1860,3090 1890,3120 1920,3120 2060,2980 2070,2980 v1(2145,2905)
  Bottom Layer w4: 2169,2549 2165,2545 2165,2502 v2(2178,2489)
  Bottom Layer w6: v1(2145,2905) 2169,2881 2169,2549
  Bottom Layer w8: J7.25@300,3500 250,3450 250,3375 275,3350 425,3350 480,3295 810,3295 879.02,3225.98 1300,3225.98 1305.98,3220 1390,3220 1420,3190 v1(1770,3190)
PQ4: J5.20 U1.A13 | length 2033.6
  Top Layer w4: U1.A13@2377.17,2340.94 2699.06,2340.94 v1(2710,2330)
  Signal Layer 3 w8: v1(2710,2330) 2730,2310 2760,2310 2810,2360 2810,2420 3030,2640 3030,3030 J5.20@3600,3600
PQ5: J5.36 U1.W12 | length 4059.6
  Top Layer w6: 1550,2410 1635,2325 1815,2325 1850.63,2360.63 U1.W12@2022.83,2360.63
  Top Layer w8: v1(1515,3275) 1560,3230 1560,3070 1550,3060 1550,2410
  Signal Layer 3 w8: v1(1515,3275) 1540,3300 1540,3325 1510,3355 1510,3395 1755,3640 2840,3640 J5.36@3600,4400
PQ6: J5.23 U1.U15 | length 3152.2
  Top Layer w6: U1.U15@2062.2,2301.57 2062.2,2286.8 v2(2065,2284)
  Signal Layer 2 w6: v2(1920,2245) 1920,2225 1941.85,2203.15 2103.11,2203.15 2126.26,2180 2440,2180 v1(2460,2200)
  Signal Layer 2 w8: v1(2575,2730) 2600,2705 2840,2705 v1(2860,2725)
  Signal Layer 3 w8: v1(2460,2200) 2485,2225 2485,2500 2620,2635 2620,2685 v1(2575,2730) ; v1(2860,2725) 2970,2835 2970,3145 3575,3750 3650,3750 J5.23@3700,3800
  Bottom Layer w6: v2(1920,2245) 1959,2284 v2(2065,2284)
PQ7: J5.25 U1.M3 | length 2670
  Top Layer w6: U1.M3@2160.63,2537.8 v2@2179.2,2537.8
  Signal Layer 2 w8: v1(2130,2955) 2155,2955 2180,2930 2335,2930 2360,2905 2660,2905 2675,2920 v1(2675,2915)
  Signal Layer 3 w8: v1(2925,2900) 2925,3200 3575,3850 3650,3850 J5.25@3700,3900
  Bottom Layer w6: v1(2130,2955) 2155,2955 2180,2930 v2(2180,2537)
  Bottom Layer w8: v1(2675,2915) 2690,2900 v1(2925,2900)
PR0: J9.5 U1.N5 | length 4133.9
  Top Layer w6: v2(2140,2479) 2140.94,2479.94 U1.N5@2140.94,2498.43
  Signal Layer 2 w8: v1(2105,2880) 2390,2880 2400,2890 2780,2890 3040,2630 3365,2630 3420,2575 3745,2575 3780,2540 3780,1040 3805,1015 3805,980 3780,955 v1(3780,800)
  Bottom Layer w4: v2(2140,2479) 2156,2495 2156,2553.48
  Bottom Layer w6: v1(2105,2880) 2140,2880 2156,2864 2156,2553.48
  Bottom Layer w8: J9.5@3700,800 v1(3780,800)
PR1: J9.3 U1.N4 | length 3881.3
  Top Layer w6: v2(2122,2499) 2122,2499.17 U1.N4@2140.94,2518.11
  Signal Layer 2 w8: v1(2115,2765) 2125,2775 2845,2775 3020,2600 3345,2600 3400,2545 3725,2545 3750,2520 3750,750 J9.3@3700,700
  Bottom Layer w6: v1(2115,2765) 2115,2636 2122,2629 v2(2122,2499)
PR2: J9.6 U1.N2 | length 4421.6
  Top Layer w4: 2129.26,2599.26 2129.26,2569.17 U1.N2@2140.94,2557.48
  Top Layer w6: v1(1965,2850) 1990,2825 1990,2790 2129.26,2650.74 2129.26,2599.26
  Signal Layer 2 w8: v1(1965,2850) 2130,3015 2470,3015 2515,2970 2750,2970 3060,2660 3385,2660 3440,2605 3765,2605 3810,2560 3810,1080 3830,1060 3830,975 3805,950 v1(3805,850)
  Bottom Layer w8: J9.6@3600,800 3650,850 v1(3805,850)
PR3: J9.12 U1.V8 | length 3329.8
  Top Layer w4: 2003.15,2445 2008.78,2439.37 U1.V8@2042.52,2439.37
  Top Layer w6: v1(1660,2385) 1720,2445 2003.15,2445
  Top Layer w8: v1(3440,1335) 3465,1335 3550,1250 3550,1150 J9.12@3600,1100
  Signal Layer 2 w8: v1(1660,1920) 1825,1755 2100,1755 2125,1730 2285,1730 2360,1655 3235,1655 3350,1540 3385,1540 v1(3405,1520)
  Signal Layer 3 w6: v1(1660,1920) 1675,1935 1675,2370 v1(1660,2385)
  Signal Layer 3 w8: v1(3405,1520) 3405,1445 3460,1390 3460,1355 v1(3440,1335)
PR4: J9.9 U1.P3 | length 3720.4
  Top Layer w4: v2@2140.8,2537.8 v2(2141,2538)
  Top Layer w6: U1.P3@2121.26,2537.8 v2@2140.8,2537.8
  Signal Layer 2 w8: v1(2130,2815) 2180,2865 2410,2865 2420,2875 2770,2875 3030,2615 3355,2615 3410,2560 3735,2560 3765,2530 3765,1015 v1(3780,1000)
  Bottom Layer w6: v1(2130,2815) 2141,2804 v2(2141,2538)
  Bottom Layer w8: J9.9@3700,1000 v1(3780,1000)
PR5: J9.10 U1.P2 | length 4151
  Top Layer w4: 2115,2600 2115,2593.16 2121.26,2586.9 U1.P2@2121.26,2557.48
  Top Layer w6: v1(1965,2815) 1965,2795 2115,2645 2115,2600
  Signal Layer 2 w8: v1(1965,2815) 2105,2955 2105,2965 2140,3000 2415,3000 2460,2955 2740,2955 3050,2645 3375,2645 3430,2590 3755,2590 3795,2550 3795,1060 v1(3805,1050)
  Bottom Layer w8: J9.10@3600,1000 3650,1050 v1(3805,1050)
PR6: J9.13 U1.W9 | length 3188.5
  Top Layer w6: v1(1730,2385) 1764.69,2419.69 U1.W9@2022.83,2419.69
  Signal Layer 2 w8: v1(1730,1920) 1785,1865 1785,1850 1850,1785 2120,1785 2145,1760 2305,1760 2380,1685 3255,1685 3355,1585 v1(3385,1585)
  Signal Layer 3 w6: v1(1730,1920) 1730,2050 1740,2060 1740,2110 1730,2120 v1(1730,2385)
  Signal Layer 3 w8: v1(3385,1585) 3385,1570 3340,1525 3340,1470 v1(3435,1375)
  Bottom Layer w8: v1(3435,1375) 3560,1250 3650,1250 J9.13@3700,1200
PR7: J9.14 U1.R10 | length 3619.5
  Top Layer w6: v2(2085,2380) 2101.57,2396.57 U1.R10@2101.57,2400
  Signal Layer 2 w8: v1(1830,1935) 1830,1880 1880,1830 2150,1830 2175,1805 2408.82,1805 2483.82,1730 3285,1730 3360,1655 v1(3385,1655)
  Signal Layer 3 w6: v1(1605,2465) 1610,2465 1665,2410 1810,2410 1825,2395 1825,2375 1815,2365 1815,1950 v1(1830,1935)
  Signal Layer 3 w8: v1(3385,1655) 3385,1625 3305,1545 3305,1430 v1(3400,1335)
  Bottom Layer w6: v1(1605,2465) 1625,2465 1650.63,2439.37 1820.63,2439.37 1860,2400 2076,2400 2085,2391 v2(2085,2380)
  Bottom Layer w8: v1(3400,1335) 3535,1200 J9.14@3600,1200
PS0: J9.29 U1.D12 | length 1818.9
  Top Layer w6: v2(2288.58,2383.08) 2289.92,2383.08 2312.37,2360.63 U1.D12@2318.11,2360.63 ; v1(2665,2405) 2700,2440 2750,2440 2910,2280
  Top Layer w8: 2910,2280 3535,2280 3565,2250 3625,2250 3650,2225 3650,2050 J9.29@3700,2000
  Bottom Layer w6: v2(2288.58,2383.08) 2306.5,2401 2377.85,2401 2411.85,2435 2548.37,2435 2575,2408.37 2575,2390.32 2590.32,2375 2635,2375 v1(2665,2405)
PS1: J9.30 U1.D13 | length 1431.4
  Top Layer w6: U1.D13@2318.11,2340.94 2337.94,2340.94 v2(2338,2341)
  Top Layer w8: v1(2835,2175) 2855,2155 v1(2955,2155) ; v1(3070,2165) 3095,2165 3125,2135 3154.57,2135 3159.57,2130 3470,2130 J9.30@3600,2000
  Bottom Layer w6: v2(2338,2341) 2357.43,2341 2383.43,2315 2410,2315 2425,2300 2475,2300 2590,2185 2825,2185 v1(2835,2175)
  Bottom Layer w8: v1(2955,2155) 3060,2155 v1(3070,2165)
PS2: J5.19 U1.B14 | length 2204.6
  Top Layer w4: U1.B14@2357.48,2321.26 2369.17,2309.57 2420,2309.57 2424.57,2305
  Top Layer w6: 2424.57,2305 2429.57,2300 2475,2300 2485,2290 2690,2290 2710,2270 v1(2790,2270)
  Signal Layer 3 w8: v1(2790,2270) 2790,2310 2830,2350 2830,2410 3050,2630 3050,3025 3575,3550 3650,3550 J5.19@3700,3600
PS3: J9.32 U1.A14 | length 1314.5
  Top Layer w4: U1.A14@2377.17,2321.26 2435,2321.26
  Top Layer w6: 2435,2321.26 2441.26,2315 2480,2315 2490,2305 2700,2305 2705,2300 2800,2300 2840,2260
  Top Layer w8: 2840,2260 2875,2260 2890,2245 3050,2245 3145,2150 3550,2150 J9.32@3600,2100
PS4: J9.15 U1.V9 | length 3155.2
  Top Layer w4: 1995,2431.37 2030.83,2431.37 U1.V9@2042.52,2419.69
  Top Layer w6: v1(1695,2385) 1741.37,2431.37 1995,2431.37
  Top Layer w8: v1(3475,1415) 3540,1350 3650,1350 J9.15@3700,1300
  Signal Layer 2 w8: v1(1695,1920) 1770,1845 1770,1840 1840,1770 2110,1770 2135,1745 2295,1745 2370,1670 3245,1670 3360,1555 v1(3420,1555)
  Signal Layer 3 w6: v1(1695,1920) 1695,2065 1690,2070 1690,2105 1695,2110 v1(1695,2385)
  Signal Layer 3 w8: v1(3420,1555) 3435,1540 3435,1455 v1(3475,1415)
PS5: J9.16 U1.T13 | length 3973
  Top Layer w6: v2(2062,2341) 2062.06,2340.94 U1.T13@2081.89,2340.94
  Top Layer w8: v1(1285,2070) 1260,2095 1260,2120 1275,2135 1290,2135 1310,2155 1310,2180 v1(1465,2335)
  Signal Layer 2 w8: v1(1285,2070) 1285,2040 1300,2025 1335,2025 1470,1890 1470,1830 1680,1620 1960,1620 2020,1560 2115,1560 2145,1530 2215,1530 2420,1325 v1(2605,1325) ; v1(2850,1570) 2860,1580 3150,1580 v1(3250,1480)
  Bottom Layer w6: v1(1465,2335) 1535,2335 1538,2338 1602,2338 ; 1602,2341 v2(2062,2341)
  Bottom Layer w8: v1(2605,1325) 2605,1380 2675,1450 2825,1450 2850,1475 v1(2850,1570) ; v1(3250,1480) 3310,1420 3430,1420 3550,1300 J9.16@3600,1300
PS6: J9.17 U1.U10 | length 3474.7
  Top Layer w6: U1.U10@2062.2,2400 2066,2400 v2(2086,2420)
  Signal Layer 2 w8: v1(1875,1895) 1910,1860 2170,1860 2195,1835 2430,1835 2505,1760 3320,1760 v1(3375,1705)
  Signal Layer 3 w6: v1(1640,2500) 1700,2440 1820,2440 1855,2405 1855,2220 1880,2195 1880,1955 1890.02,1944.98 1890.02,1902.5 1882.52,1895 v1(1875,1895)
  Bottom Layer w4: 2050,2436 2070,2436 v2(2086,2420)
  Bottom Layer w6: v1(1640,2500) 1670,2470 1830,2470 1864,2436 2050,2436
  Bottom Layer w8: v1(3375,1705) 3398,1682 3443,1682 3570,1555 3720,1555 3750,1525 3750,1450 J9.17@3700,1400
PS7: J9.18 U1.R13 | length 3645.7
  Top Layer w6: U1.R13@2101.57,2340.94 2115.06,2340.94 v2(2121,2335)
  Top Layer w8: v1(1285,2105) 1330,2150 1330,2175 1460,2305 v1(1490,2305)
  Signal Layer 2 w8: v1(1285,2105) 1300,2105 1320,2085 1345,2085 1355,2075 1405,2075 1530,1950 1530,1870 1720,1680 2000,1680 2060,1620 2155,1620 2185,1590 2275,1590 2290,1575 2335,1575 2355,1595 3170,1595 v1(3250,1515)
  Bottom Layer w6: v1(1490,2305) 1528.89,2305 1551.89,2328 2041,2328 2044,2325 2068.63,2325 2084.57,2340.94 2115.06,2340.94 v2(2121,2335)
  Bottom Layer w8: v1(3250,1515) 3295,1515 3355,1455 3545,1455 J9.18@3600,1400
PT0: J9.19 U1.W10 | length 2916.2
  Top Layer w6: v1(1765,2385) 1789.69,2409.69 2013.15,2409.69 U1.W10@2022.83,2400
  Signal Layer 2 w8: v1(1765,1920) 1800,1885 1800,1860 1860,1800 2130,1800 2155,1775 2315,1775 2390,1700 3265,1700 3355,1610 3400,1610 v1(3420,1590)
  Signal Layer 3 w6: v1(1765,1920) 1765,2115 1750,2130 1750,2263.78 1748,2265.78 1748,2308 1765,2325 v1(1765,2385)
  Bottom Layer w8: v1(3420,1590) 3435,1590 3575,1450 3650,1450 J9.19@3700,1500
PT1: J9.20 U1.V10 | length 2717.6
  Top Layer w4: v1(1800,2385) 1814.69,2399.69 2003.63,2399.69 2015,2388.32 2030.83,2388.32 U1.V10@2042.52,2400
  Signal Layer 2 w8: v1(1800,1920) 1815,1905 1815,1870 1870,1815 2140,1815 2165,1790 2325,1790 2400,1715 3275,1715 3365,1625 v1(3420,1625)
  Signal Layer 3 w6: v1(1800,1920) v1(1800,2385)
  Bottom Layer w8: v1(3420,1625) 3475,1625 J9.20@3600,1500
PT2: J9.27 U1.E18 | length 1845.5
  Top Layer w4: U1.E18@2298.43,2242.52 2286.74,2230.83 2286.74,2198.26 2370,2115 v1(2370,2100)
  Top Layer w8: v1(3420,1810) 3510,1810 3570,1750 3630,1750 3650,1770 3650,1850 J9.27@3700,1900
  Signal Layer 2 w8: v1(2370,2100) 2410,2060 2410,1970 2495,1885 2495,1846.1 2536.1,1805 3415,1805 v1(3420,1810)
PT3: J9.28 U1.F17 | length 1860.7
  Top Layer w6: U1.F17@2278.74,2262.2 2298,2281.46 v2(2298,2282)
  Top Layer w8: v1(3420,1775) 3395,1800 3395,1895 3410,1910 3590,1910 J9.28@3600,1900
  Signal Layer 2 w8: v1(2370,2065) 2395,2040 2395,1960 2475,1880 2475,1840 2525,1790 3405,1790 v1(3420,1775)
  Bottom Layer w4: v2(2298,2282) 2298,2259.79 2301,2256.79 2301,2242 2308,2235
  Bottom Layer w6: 2308,2235 2308,2164 2345,2127 2345,2090 v1(2370,2065)
RBIAS: R6.2 U1.W15 | length 263.8
  Top Layer w4: 2003.15,2290 2011.26,2290 U1.W15@2022.83,2301.57
  Top Layer w6: R6.2@1851.5,2130 1880,2158.5 1880,2195 1895,2210 1915,2210 1995,2290 2003.15,2290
